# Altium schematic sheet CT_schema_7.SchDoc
size 277 x 170 mm
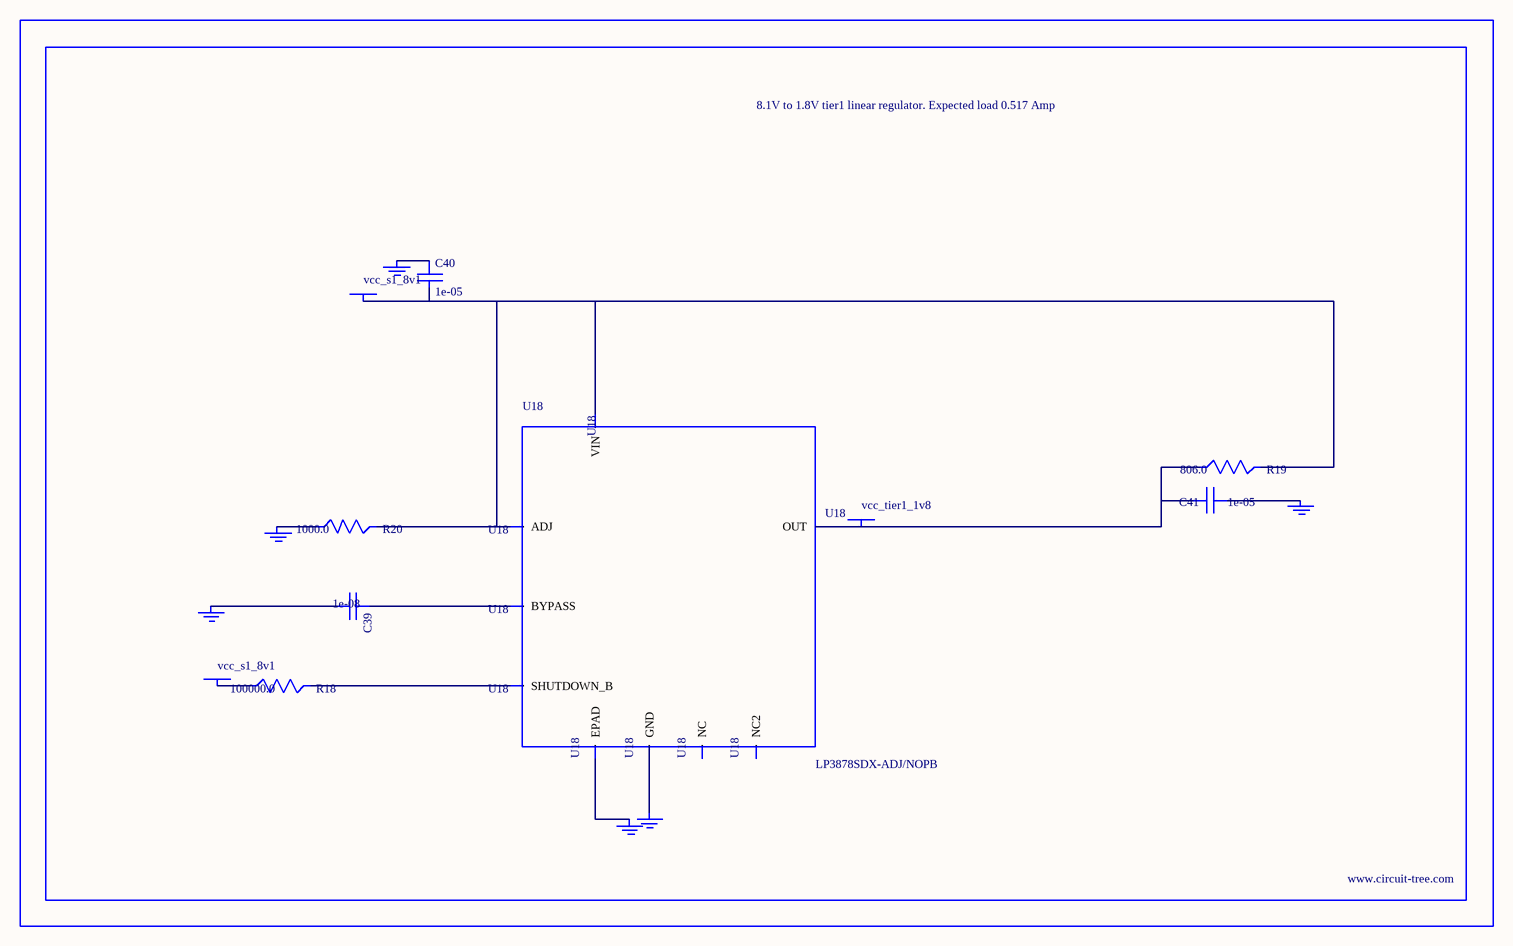
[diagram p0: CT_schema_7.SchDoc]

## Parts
BORDER6  (no value)
C39  1e-08  [C0402]
C40  1e-05  [C1206]
C41  1e-05  [C0805]
GND_INSTANCE_6_0  (no value)
GND_INSTANCE_6_1  (no value)
GND_INSTANCE_6_2  (no value)
GND_INSTANCE_6_3  (no value)
GND_INSTANCE_6_4  (no value)
GND_INSTANCE_6_5  (no value)
POWER_INSTANCE_6_0  vcc_s1_8v1
POWER_INSTANCE_6_1  vcc_s1_8v1
POWER_INSTANCE_6_2  vcc_tier1_1v8
R18  100000.0  [R0603]
R19  806.0  [R0603]
R20  1000.0  [R0603]
U18  LP3878SDX-ADJ/NOPB  [WSON-8]

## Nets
NetC39_1: C39.1 U18.1(BYPASS)
NetC39_2: C39.2 GND_INSTANCE_6_0.0(GND)
NetC40_1: C40.1 GND_INSTANCE_6_1.0(GND)
NetC40_2: C40.2 POWER_INSTANCE_6_0.0(PWR) R19.2 R20.2 U18.4(VIN) U18.6(ADJ)
NetC41_1: C41.1 GND_INSTANCE_6_2.0(GND)
NetC41_2: C41.2 POWER_INSTANCE_6_2.0(PWR) R19.1 U18.5(OUT)
NetGND_INSTANCE_6_3_0: GND_INSTANCE_6_3.0(GND) R20.1
NetGND_INSTANCE_6_4_0: GND_INSTANCE_6_4.0(GND) U18.PAD(EPAD)
NetGND_INSTANCE_6_5_0: GND_INSTANCE_6_5.0(GND) U18.3(GND)
NetPOWER_INSTANCE_6_1_0: POWER_INSTANCE_6_1.0(PWR) R18.1
NetR18_2: R18.2 U18.8(SHUTDOWN_B)

Not connected (* = marked no-connect by the designer): U18 2(NC) 7(NC2)

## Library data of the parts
BORDER6 = BORDER_PAGE6
C39 = C0402C103K3RAC
C40 = C1206C106K3RACTU
C41 = GRM219R60J106ME19D
GND_INSTANCE_6_0-GND_INSTANCE_6_5 = GND
POWER_INSTANCE_6_0-POWER_INSTANCE_6_2 = PWR
R18 = RC0603JR-07100KL
R19 = ERJ-3EKF8060V
R20 = RC0603JR-071KL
